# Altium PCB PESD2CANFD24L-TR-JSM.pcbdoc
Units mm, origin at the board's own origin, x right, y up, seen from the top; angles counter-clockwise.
Board outline 15.76 x 15.75 mm, 2 copper layers (Top Layer, Bottom Layer), stack 0 mm thick; 1 components, 0 nets, 3 pads, 0 vias.
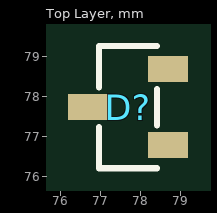
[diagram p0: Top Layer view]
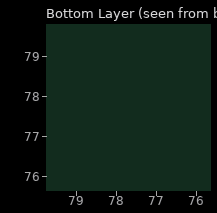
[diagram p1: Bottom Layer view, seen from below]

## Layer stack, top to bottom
Top Layer: signal copper (thickness not stored)
Bottom Layer: signal copper (thickness not stored)

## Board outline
85.61,69.85 69.85,69.85 69.85,85.602 85.61,85.602

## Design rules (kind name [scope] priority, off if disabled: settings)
PasteMaskExpansion "Paste Mask Expansion" [All] p1: expansion=0
SolderMaskExpansion "Solder Mask Expansion" [IsVia] p1: expansion=-25.4 istentingtop=TRUE
SolderMaskExpansion "Solder Mask Expansion" [All] p2: expansion=0.051 istentingtop=FALSE

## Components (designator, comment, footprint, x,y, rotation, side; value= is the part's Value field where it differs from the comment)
D? "PESD2CANFD24L-TR-JSM" SOT-23-3_L2.9-W1.3-P1.90-LS2.4-BR 77.7,77.726 r0 top

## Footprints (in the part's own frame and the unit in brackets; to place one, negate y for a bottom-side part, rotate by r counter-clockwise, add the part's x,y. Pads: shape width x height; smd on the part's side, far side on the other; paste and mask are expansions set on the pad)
SOT-23-3_L2.9-W1.3-P1.90-LS2.4-BR [mm]
  rect 1x0.65 smd: 1(1,-0.95) 2(1,0.95) 3(-1,0)
  silkscreen extent -0.73,-1.53 0.73,1.53

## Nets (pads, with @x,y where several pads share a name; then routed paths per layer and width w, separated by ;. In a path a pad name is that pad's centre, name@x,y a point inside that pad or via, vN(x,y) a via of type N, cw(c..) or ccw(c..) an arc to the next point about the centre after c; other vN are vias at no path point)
pads on no net: D?.1 D?.2 D?.3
